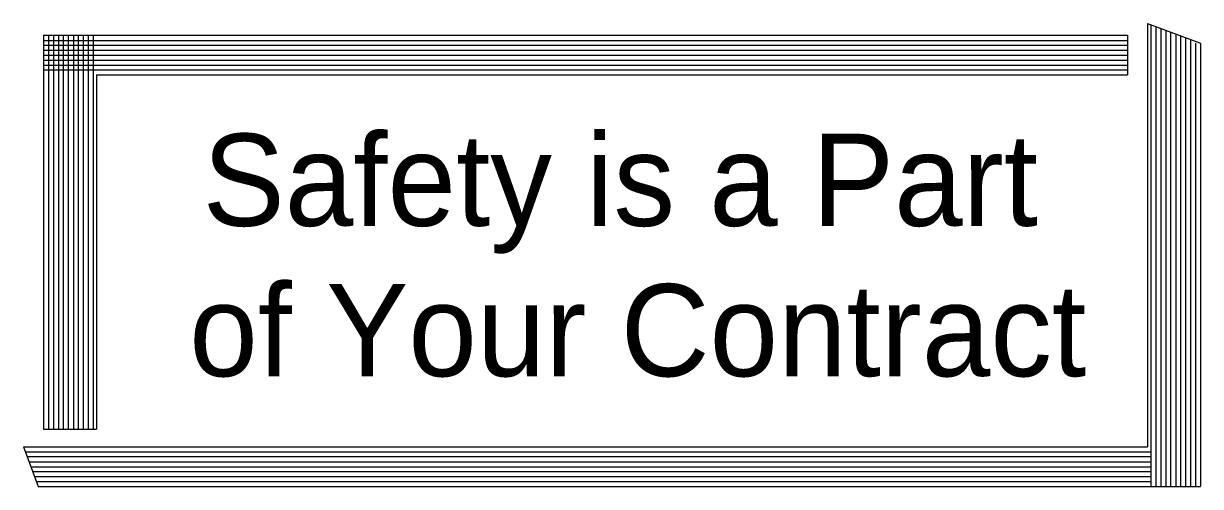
# Model space of a CAD drawing. Extents: x -11983 to -11903, y -13969.5 to -13913.5.
# Drawn here: x -11927.12 to -11919.7, y -13959.08 to -13956.16 of the extents above; entities that cross this region are included whole.
import ezdxf

# ---------------------------------------------------------------- set-up
doc = ezdxf.new("R2010")
doc.units = 0
doc.layers.add('Level 1', color=7, linetype='Continuous')

msp = doc.modelspace()

# ---------------------------------------------------------------- linework, layer by layer
at = {"layer": 'Level 1'}
for p, q in [((-11920.0331, -13956.1577), (-11920.0331, -13958.8257)), ((-11920.0331, -13956.1577), (-11919.6991, -13956.2817)), ((-11920.0111, -13956.1657), (-11920.0111, -13959.0757)), ((-11919.9811, -13956.1777), (-11919.9811, -13959.0757)), ((-11919.9491, -13956.1897), (-11919.9491, -13959.0757)), ((-11919.9171, -13956.2017), (-11919.9171, -13959.0757)), ((-11926.9931, -13956.2317), (-11920.1591, -13956.2317)), ((-11926.9931, -13956.2317), (-11926.9931, -13958.7137)), ((-11926.9931, -13956.2637), (-11920.1591, -13956.2637)), ((-11926.9611, -13956.2317), (-11926.9611, -13958.7137)), ((-11926.9311, -13956.2317), (-11926.9311, -13958.7137)), ((-11926.8991, -13956.2317), (-11926.8991, -13958.7137)), ((-11926.8691, -13956.2317), (-11926.8691, -13958.7137)), ((-11926.8371, -13956.2317), (-11926.8371, -13958.7137)), ((-11926.8051, -13956.2317), (-11926.8051, -13958.7137)), ((-11926.7751, -13956.2317), (-11926.7751, -13958.7137)), ((-11926.7431, -13956.2317), (-11926.7431, -13958.7137)), ((-11926.7111, -13956.2317), (-11926.7111, -13958.7137)), ((-11926.6811, -13956.2317), (-11926.6811, -13958.7137)), ((-11920.1591, -13956.2317), (-11920.1591, -13956.4817)), ((-11919.8871, -13956.2117), (-11919.8871, -13959.0757)), ((-11919.8551, -13956.2237), (-11919.8551, -13959.0757)), ((-11919.8251, -13956.2357), (-11919.8251, -13959.0757)), ((-11919.7931, -13956.2477), (-11919.7931, -13959.0757)), ((-11919.7611, -13956.2577), (-11919.7611, -13959.0757)), ((-11926.9931, -13956.2937), (-11920.1591, -13956.2937)), ((-11926.9931, -13956.3257), (-11920.1591, -13956.3257)), ((-11919.7311, -13956.2817), (-11919.7311, -13959.0757)), ((-11919.6991, -13956.2817), (-11919.6991, -13959.0757)), ((-11926.9931, -13956.3577), (-11920.1591, -13956.3577)), ((-11926.9931, -13956.3877), (-11920.1591, -13956.3877)), ((-11926.9931, -13956.4197), (-11920.1591, -13956.4197)), ((-11926.9931, -13956.4497), (-11920.1591, -13956.4497)), ((-11926.6591, -13956.4817), (-11920.1591, -13956.4817)), ((-11926.6591, -13956.4817), (-11926.6591, -13958.7137)), ((-11926.9931, -13958.7137), (-11926.6591, -13958.7137)), ((-11927.1191, -13958.8257), (-11920.0331, -13958.8257)), ((-11927.1191, -13958.8257), (-11927.0271, -13959.0757)), ((-11927.1071, -13958.8577), (-11920.0111, -13958.8577)), ((-11927.0971, -13958.8877), (-11920.0111, -13958.8877)), ((-11927.0851, -13958.9197), (-11920.0111, -13958.9197)), ((-11927.0731, -13958.9517), (-11920.0111, -13958.9517)), ((-11927.0611, -13958.9817), (-11920.0111, -13958.9817)), ((-11927.0491, -13959.0137), (-11920.0111, -13959.0137)), ((-11927.0391, -13959.0437), (-11920.0111, -13959.0437)), ((-11927.0271, -13959.0757), (-11919.6991, -13959.0757))]:
    msp.add_line(p, q, dxfattribs=at)

# ---------------------------------------------------------------- texts
for s, p in [('Safety is a Part', (-11925.9901, -13957.4332)), ('of Your Contract', (-11926.0744, -13958.381))]:
    msp.add_text(s, height=0.580751, dxfattribs=at).set_placement(p)

doc.saveas('drawing.dxf')
